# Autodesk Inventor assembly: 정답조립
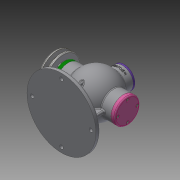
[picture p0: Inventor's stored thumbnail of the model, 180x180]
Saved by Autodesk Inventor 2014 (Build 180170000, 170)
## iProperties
Created: 2020-08
Part Number: 정답조립
Document SubType Name: Assembly
Designer: kh
Author: kh
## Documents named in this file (18)
- C:\Users\kh\Desktop\700806V1031\정답조립.iam
- C:\Users\kh\Desktop\700806V1031\본체.ipt
- C:\Users\kh\Desktop\700806V1031\V-벨트풀리.ipt
- C:\Users\kh\Desktop\700806V1031\너트 M8.ipt
- C:\Users\kh\Desktop\700806V1031\뒤커버.ipt
- C:\Users\kh\Desktop\700806V1031\멈춤링 15x1.ipt
- C:\Users\kh\Desktop\700806V1031\멈춤링 35x1.6.ipt
- 멈춤링 35x1.6.ipt
- C:\Users\kh\Desktop\700806V1031\베어링 6202.ipt
- 베어링 6202.ipt
- C:\Users\kh\Desktop\700806V1031\볼트 M4.ipt
- C:\Users\kh\Desktop\700806V1031\상부커버.ipt
- C:\Users\kh\Desktop\700806V1031\슬라이드.ipt
- C:\Users\kh\Desktop\700806V1031\앞커버.ipt
- C:\Users\kh\Desktop\700806V1031\오일 실 15 30 7.ipt
- C:\Users\kh\Desktop\700806V1031\칼라.ipt
- C:\Users\kh\Desktop\700806V1031\키 3x3x12.ipt
- C:\Users\kh\Desktop\700806V1031\편심축.ipt
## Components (1 placed, 1 different names)
1. V-벨트풀리:1 — Insert:16, Mate:2, Insert:19
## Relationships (3: Insert 2, Mate 1)
- Insert:16: V-벨트풀리:1
- Mate:2: V-벨트풀리:1
- Insert:19: V-벨트풀리:1
